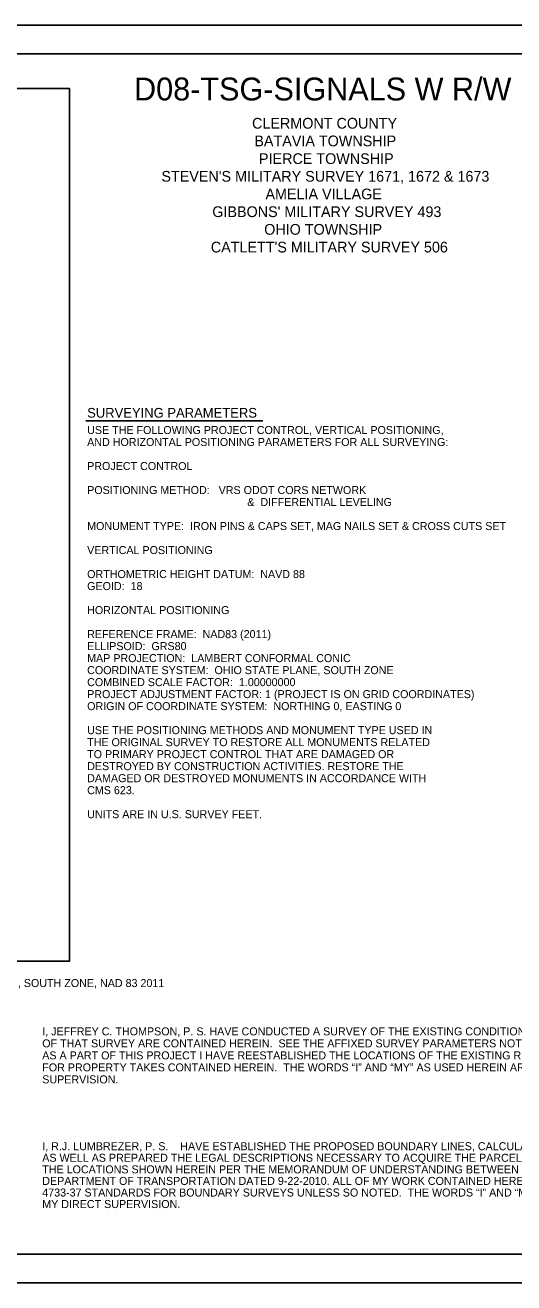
# Model space of a CAD drawing. Extents: x -10.5 to 54.7, y 0 to 22.
# Drawn here: x 11.55 to 20.1, y 0 to 22 of the extents above; entities that cross this region are included whole.
import ezdxf

# ---------------------------------------------------------------- set-up
doc = ezdxf.new("R2010")
doc.units = 0
for name, color, linetype in [('SH_Border', 7, 'Continuous'), ('SH_Cut_Line', 7, 'Continuous'), ('SH_Data', 7, 'Continuous'), ('SH_Text', 7, 'Continuous')]:
    doc.layers.add(name, color=color, linetype=linetype)

msp = doc.modelspace()

# ---------------------------------------------------------------- linework, layer by layer
at = {"layer": 'SH_Border'}
msp.add_lwpolyline([(1.5, 21.5), (33.5, 21.5), (33.5, 0.5), (1.5, 0.5)], close=True, dxfattribs=at)
at = {"layer": 'SH_Cut_Line'}
msp.add_lwpolyline([(0, 0), (34, 0), (34, 22), (0, 22)], close=True, dxfattribs=at)
at = {"layer": 'SH_Data'}
msp.add_lwpolyline([(1.634, 20.891), (12.33, 20.891), (12.33, 5.628), (1.634, 5.628)], close=True, dxfattribs=at)
at = {"layer": 'SH_Text'}
msp.add_line((12.615, 15.077), (15.708, 15.077), dxfattribs=at)
msp.add_lwpolyline([(1.634, 5.628), (12.33, 5.628), (12.33, 20.891), (1.634, 20.891)], close=True, dxfattribs=at)

# ---------------------------------------------------------------- texts
for s, height, p in [('D08-TSG-SIGNALS W R/W', 0.4, (13.456, 20.683)), ('CLERMONT COUNTY', 0.1875, (15.519, 20.19)), ('BATAVIA TOWNSHIP', 0.1875, (15.559, 19.881)), ('PIERCE TOWNSHIP', 0.1875, (15.64, 19.571)), ("STEVEN'S MILITARY SURVEY 1671, 1672 & 1673", 0.1875, (13.934, 19.262)), ('AMELIA VILLAGE', 0.1875, (15.753, 18.953)), ("GIBBONS' MILITARY SURVEY 493", 0.1875, (14.824, 18.643)), ('OHIO TOWNSHIP', 0.1875, (15.731, 18.334)), ("CATLETT'S MILITARY SURVEY 506", 0.1875, (14.798, 18.024)), ('SURVEYING PARAMETERS', 0.17, (12.636, 15.134)), ('USE THE FOLLOWING PROJECT CONTROL, VERTICAL POSITIONING,', 0.14, (12.636, 14.848)), ('AND HORIZONTAL POSITIONING PARAMETERS FOR ALL SURVEYING:', 0.14, (12.636, 14.638)), ('PROJECT CONTROL', 0.14, (12.636, 14.218)), ('POSITIONING METHOD:   VRS ODOT CORS NETWORK', 0.14, (12.636, 13.798)), ('&  DIFFERENTIAL LEVELING', 0.14, (15.436, 13.588)), ('MONUMENT TYPE:  IRON PINS & CAPS SET, MAG NAILS SET & CROSS CUTS SET', 0.14, (12.636, 13.168)), ('VERTICAL POSITIONING', 0.14, (12.636, 12.748)), ('ORTHOMETRIC HEIGHT DATUM:  NAVD 88', 0.14, (12.636, 12.328)), ('GEOID:  18', 0.14, (12.636, 12.118)), ('HORIZONTAL POSITIONING', 0.14, (12.636, 11.698)), ('REFERENCE FRAME:  NAD83 (2011)', 0.14, (12.636, 11.278)), ('ELLIPSOID:  GRS80', 0.14, (12.636, 11.068)), ('COORDINATE SYSTEM:  OHIO STATE PLANE, SOUTH ZONE', 0.14, (12.636, 10.648)), ('MAP PROJECTION:  LAMBERT CONFORMAL CONIC', 0.14, (12.636, 10.858)), ('COMBINED SCALE FACTOR:  1.00000000', 0.14, (12.636, 10.438)), ('PROJECT ADJUSTMENT FACTOR: 1 (PROJECT IS ON GRID COORDINATES)', 0.14, (12.636, 10.228)), ('ORIGIN OF COORDINATE SYSTEM:  NORTHING 0, EASTING 0', 0.14, (12.636, 10.018)), ('USE THE POSITIONING METHODS AND MONUMENT TYPE USED IN', 0.14, (12.636, 9.598)), ('THE ORIGINAL SURVEY TO RESTORE ALL MONUMENTS RELATED', 0.14, (12.636, 9.388)), ('TO PRIMARY PROJECT CONTROL THAT ARE DAMAGED OR', 0.14, (12.636, 9.178)), ('DESTROYED BY CONSTRUCTION ACTIVITIES. RESTORE THE', 0.14, (12.636, 8.968)), ('DAMAGED OR DESTROYED MONUMENTS IN ACCORDANCE WITH', 0.14, (12.636, 8.758)), ('CMS 623.', 0.14, (12.636, 8.548)), ('UNITS ARE IN U.S. SURVEY FEET.', 0.14, (12.636, 8.128)), ('COORDINATES SHOWN ARE RELATIVE TO GRID SOUTH OF THE OHIO STATE PLANE COORDINATE SYSTEM, SOUTH ZONE, NAD 83 2011', 0.14, (1.637, 5.174)), ('I, JEFFREY C. THOMPSON, P. S. HAVE CONDUCTED A SURVEY OF THE EXISTING CONDITIONS FOR THE OHIO DEPARTMENT OF TRANSPORTATION IN APRIL OF 2020. THE RESULTS', 0.14, (11.851, 4.329)), ('OF THAT SURVEY ARE CONTAINED HEREIN.  SEE THE AFFIXED SURVEY PARAMETERS NOTE FOR THE HORIZONTAL AND VERTICAL SURVEY PARAMETERS USED FOR THIS PROJECT.', 0.14, (11.851, 4.119)), ('AS A PART OF THIS PROJECT I HAVE REESTABLISHED THE LOCATIONS OF THE EXISTING RIGHT OF WAY, EXISTING BOUNDARY LINES, AND CENTERLINE OF EXISTING RIGHT OF WAY', 0.14, (11.851, 3.909)), ('FOR PROPERTY TAKES CONTAINED HEREIN.  THE WORDS “I” AND “MY” AS USED HEREIN ARE TO MEAN THAT EITHER MYSELF OR SOMEONE WORKING UNDER MY DIRECT', 0.14, (11.851, 3.699)), ('SUPERVISION.', 0.14, (11.851, 3.489)), ('I, R.J. LUMBREZER, P. S.  ', 0.14, (11.851, 2.32)), ('HAVE ESTABLISHED THE PROPOSED BOUNDARY LINES, CALCULATED THE GROSS TAKE, PRESENT ROADWAY OCCUPIED (PRO), NET TAKE AND NET RESIDUE;', 0.14, (14.264, 2.32)), ('AS WELL AS PREPARED THE LEGAL DESCRIPTIONS NECESSARY TO ACQUIRE THE PARCELS AS SHOWN HEREIN.  AS A PART OF THIS WORK, RIGHT OF WAY MONUMENTS WILL BE SET AT', 0.14, (11.851, 2.118)), ('THE LOCATIONS SHOWN HEREIN PER THE MEMORANDUM OF UNDERSTANDING BETWEEN THE BOARD OF REGISTRATION FOR ENGINEERS AND SURVEYORS AND THE OHIO', 0.14, (11.851, 1.915)), ('DEPARTMENT OF TRANSPORTATION DATED 9-22-2010. ALL OF MY WORK CONTAINED HEREIN WAS CONDUCTED IN ACCORDANCE WITH THE OHIO ADMINISTRATIVE CODE CHAPTER', 0.14, (11.851, 1.713)), ('4733-37 STANDARDS FOR BOUNDARY SURVEYS UNLESS SO NOTED.  THE WORDS “I” AND “MY” AS USED HEREIN ARE TO MEAN THAT EITHER MYSELF OR SOMEONE WORKING UNDER', 0.14, (11.851, 1.51)), ('MY DIRECT SUPERVISION.', 0.14, (11.851, 1.308))]:
    msp.add_text(s, height=height, dxfattribs=at).set_placement(p)

doc.saveas('drawing.dxf')
